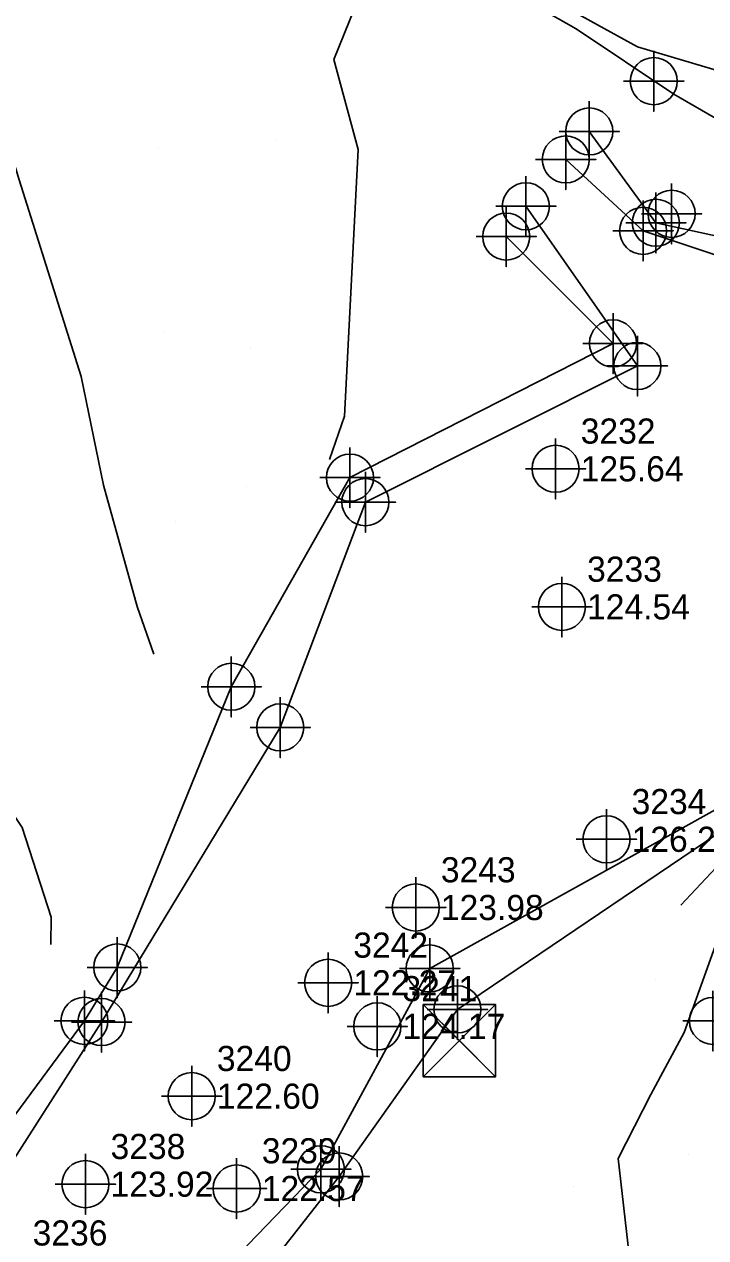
# Model space of a CAD drawing. Extents: x 2312183 to 2312663, y 819676 to 820746.
# Drawn here: x 2312397.7 to 2312465.5, y 820065.9 to 820186.5 of the extents above; entities that cross this region are included whole.
import ezdxf

# ---------------------------------------------------------------- set-up
doc = ezdxf.new("R2010")
doc.units = 0
for name, color, linetype in [('CTL Bench Mark CELL', 7, 'Continuous'), ('Exist DTM Breakline', 7, 'Continuous'), ('Exist DTM Breakline Cogo Point CELL', 7, 'Continuous'), ('Exist DTM Regular Point CELL', 7, 'Continuous'), ('Exist DTM Regular Point Underwater CELL', 7, 'Continuous'), ('Exist DTM Regular Point Underwater Cogo Elevation', 7, 'Continuous'), ('Exist DTM Regular Point Underwater Cogo Number', 7, 'Continuous'), ('Exist Hydro Stream or Body of Water', 7, 'Continuous'), ('Exist Hydro Stream or Body of Water Cogo Point CELL', 7, 'Continuous'), ('PH Exist DTM Breakline', 7, 'Continuous'), ('PH Exist DTM Point', 7, 'Continuous')]:
    doc.layers.add(name, color=color, linetype=linetype)

msp = doc.modelspace()

# ---------------------------------------------------------------- linework, layer by layer
at = {"layer": 'CTL Bench Mark CELL'}
msp.add_line((2312441.01, 820085.5), (2312441.01, 820085.5), dxfattribs=at)
msp.add_lwpolyline([(2312437.41, 820089.08), (2312444.6, 820089.08), (2312444.6, 820081.9), (2312437.41, 820081.9)], close=True, dxfattribs=at)
for points in [[(2312444.6, 820089.08), (2312437.41, 820081.9), (2312441.01, 820085.49), (2312444.6, 820081.9), (2312437.41, 820089.08)], [(2312441.01, 820085.49), (2312444.6, 820089.08), (2312437.41, 820089.08), (2312441.01, 820085.49)], [(2312441.01, 820085.49), (2312437.41, 820081.9), (2312444.6, 820081.9), (2312441.01, 820085.49)]]:
    msp.add_lwpolyline(points, dxfattribs=at)
at = {"layer": 'Exist DTM Breakline'}
for points in [[(2312453.92, 820175.89), (2312460.54, 820166.81), (2312494.29, 820159.45), (2312521.51, 820151.72), (2312518.42, 820162.59), (2312517.14, 820177.02)], [(2312445.66, 820165.44), (2312456.28, 820154.82), (2312430.12, 820141.47), (2312418.32, 820120.68), (2312406.98, 820092.77), (2312403.71, 820087.46)], [(2312398.6, 820034.89), (2312415.76, 820055.03), (2312429.05, 820071.99), (2312440.81, 820088.6), (2312469.05, 820107.68)], [(2312403.71, 820087.46), (2312374.49, 820047.93)]]:
    msp.add_lwpolyline(points, dxfattribs=at)
at = {"layer": 'Exist DTM Breakline Cogo Point CELL'}
for points in [[(2312453.92, 820178.89), (2312453.92, 820172.89), (2312453.92, 820175.89), (2312456.92, 820175.89), (2312450.92, 820175.89)], [(2312460.54, 820169.81), (2312460.54, 820163.81), (2312460.54, 820166.81), (2312463.54, 820166.81), (2312457.54, 820166.81)], [(2312445.66, 820168.44), (2312445.66, 820162.44), (2312445.66, 820165.44), (2312448.66, 820165.44), (2312442.66, 820165.44)], [(2312456.28, 820157.82), (2312456.28, 820151.82), (2312456.28, 820154.82), (2312459.28, 820154.82), (2312453.28, 820154.82)], [(2312430.12, 820144.47), (2312430.12, 820138.47), (2312430.12, 820141.47), (2312433.12, 820141.47), (2312427.12, 820141.47)], [(2312418.32, 820123.68), (2312418.32, 820117.68), (2312418.32, 820120.68), (2312421.32, 820120.68), (2312415.32, 820120.68)], [(2312406.98, 820095.77), (2312406.98, 820089.77), (2312406.98, 820092.77), (2312409.98, 820092.77), (2312403.98, 820092.77)], [(2312440.81, 820091.6), (2312440.81, 820085.6), (2312440.81, 820088.6), (2312443.81, 820088.6), (2312437.81, 820088.6)], [(2312403.71, 820090.46), (2312403.71, 820084.46), (2312403.71, 820087.46), (2312406.71, 820087.46), (2312400.71, 820087.46)], [(2312429.05, 820074.99), (2312429.05, 820068.99), (2312429.05, 820071.99), (2312432.05, 820071.99), (2312426.05, 820071.99)]]:
    msp.add_lwpolyline(points, dxfattribs=at)
for centre in [(2312453.92, 820175.89), (2312460.54, 820166.81), (2312445.66, 820165.44), (2312456.28, 820154.82), (2312430.12, 820141.47), (2312418.32, 820120.68), (2312406.98, 820092.77), (2312440.81, 820088.6), (2312403.71, 820087.46), (2312429.05, 820071.99)]:
    msp.add_circle(centre, 2.34, dxfattribs=at)
at = {"layer": 'Exist DTM Regular Point CELL'}
for points in [[(2312460.33, 820183.89), (2312460.33, 820177.89), (2312460.33, 820180.89), (2312463.33, 820180.89), (2312457.33, 820180.89)], [(2312462.11, 820170.7), (2312462.11, 820164.7), (2312462.11, 820167.7), (2312465.11, 820167.7), (2312459.11, 820167.7)], [(2312466.22, 820090.45), (2312466.22, 820084.45), (2312466.22, 820087.45), (2312469.22, 820087.45), (2312463.22, 820087.45)]]:
    msp.add_lwpolyline(points, dxfattribs=at)
for centre in [(2312460.33, 820180.89), (2312462.11, 820167.7), (2312466.22, 820087.45)]:
    msp.add_circle(centre, 2.34, dxfattribs=at)
at = {"layer": 'Exist DTM Regular Point Underwater CELL'}
for points in [[(2312450.57, 820145.35), (2312450.57, 820139.35), (2312450.57, 820142.35), (2312453.57, 820142.35), (2312447.57, 820142.35)], [(2312451.2, 820131.62), (2312451.2, 820125.62), (2312451.2, 820128.62), (2312454.2, 820128.62), (2312448.2, 820128.62)], [(2312455.63, 820108.51), (2312455.63, 820102.51), (2312455.63, 820105.51), (2312458.63, 820105.51), (2312452.63, 820105.51)], [(2312436.66, 820101.73), (2312436.66, 820095.73), (2312436.66, 820098.73), (2312439.66, 820098.73), (2312433.66, 820098.73)], [(2312427.95, 820094.24), (2312427.95, 820088.24), (2312427.95, 820091.24), (2312430.95, 820091.24), (2312424.95, 820091.24)], [(2312432.84, 820089.91), (2312432.84, 820083.91), (2312432.84, 820086.91), (2312435.84, 820086.91), (2312429.84, 820086.91)], [(2312414.38, 820082.97), (2312414.38, 820076.97), (2312414.38, 820079.97), (2312417.38, 820079.97), (2312411.38, 820079.97)], [(2312403.81, 820074.22), (2312403.81, 820068.22), (2312403.81, 820071.22), (2312406.81, 820071.22), (2312400.81, 820071.22)], [(2312418.85, 820073.79), (2312418.85, 820067.79), (2312418.85, 820070.79), (2312421.85, 820070.79), (2312415.85, 820070.79)]]:
    msp.add_lwpolyline(points, dxfattribs=at)
for centre in [(2312450.57, 820142.35), (2312451.2, 820128.62), (2312455.63, 820105.51), (2312436.66, 820098.73), (2312427.95, 820091.24), (2312432.84, 820086.91), (2312414.38, 820079.97), (2312403.81, 820071.22), (2312418.85, 820070.79)]:
    msp.add_circle(centre, 2.34, dxfattribs=at)
at = {"layer": 'Exist Hydro Stream or Body of Water'}
for points in [[(2312451.58, 820173.11), (2312459.27, 820166.01), (2312491.52, 820155.27), (2312524.63, 820151.17), (2312520.55, 820163.08), (2312522.64, 820179.93)], [(2312447.61, 820168.45), (2312458.7, 820152.57), (2312431.65, 820139.03), (2312423.18, 820116.64), (2312405.41, 820087.34)], [(2312393.18, 820036.93), (2312414.57, 820059.59), (2312427.23, 820072.7), (2312438.05, 820092.67), (2312468.54, 820109.59), (2312503.07, 820119.67), (2312550.88, 820117.01)], [(2312405.41, 820087.34), (2312377.81, 820044.19)]]:
    msp.add_lwpolyline(points, dxfattribs=at)
at = {"layer": 'Exist Hydro Stream or Body of Water Cogo Point CELL'}
for points in [[(2312448.58, 820173.11), (2312454.58, 820173.11), (2312451.58, 820173.11), (2312451.58, 820170.11), (2312451.58, 820176.11)], [(2312444.61, 820168.45), (2312450.61, 820168.45), (2312447.61, 820168.45), (2312447.61, 820165.45), (2312447.61, 820171.45)], [(2312456.27, 820166.01), (2312462.27, 820166.01), (2312459.27, 820166.01), (2312459.27, 820163.01), (2312459.27, 820169.01)], [(2312455.7, 820152.57), (2312461.7, 820152.57), (2312458.7, 820152.57), (2312458.7, 820149.57), (2312458.7, 820155.57)], [(2312428.65, 820139.03), (2312434.65, 820139.03), (2312431.65, 820139.03), (2312431.65, 820136.03), (2312431.65, 820142.03)], [(2312420.18, 820116.64), (2312426.18, 820116.64), (2312423.18, 820116.64), (2312423.18, 820113.64), (2312423.18, 820119.64)], [(2312435.05, 820092.67), (2312441.05, 820092.67), (2312438.05, 820092.67), (2312438.05, 820089.67), (2312438.05, 820095.67)], [(2312402.41, 820087.34), (2312408.41, 820087.34), (2312405.41, 820087.34), (2312405.41, 820084.34), (2312405.41, 820090.34)], [(2312424.23, 820072.7), (2312430.23, 820072.7), (2312427.23, 820072.7), (2312427.23, 820069.7), (2312427.23, 820075.7)]]:
    msp.add_lwpolyline(points, dxfattribs=at)
for centre in [(2312451.58, 820173.11), (2312447.61, 820168.45), (2312459.27, 820166.01), (2312458.7, 820152.57), (2312431.65, 820139.03), (2312423.18, 820116.64), (2312438.05, 820092.67), (2312405.41, 820087.34), (2312427.23, 820072.7)]:
    msp.add_circle(centre, 2.34, dxfattribs=at)
at = {"layer": 'PH Exist DTM Breakline'}
for points in [[(2312428.09, 820143.26), (2312429.58, 820147.58), (2312430.95, 820174.1), (2312428.5, 820183.06), (2312431.62, 820190.77), (2312435.54, 820194.22), (2312439.28, 820195.43), (2312442.83, 820191.67), (2312452.63, 820186.08), (2312462.34, 820179.59)], [(2312443.92, 820193.42), (2312449.14, 820189.59), (2312458.71, 820184.29), (2312471.76, 820180.42), (2312480.71, 820178.26), (2312488.13, 820176.64), (2312494.81, 820169.91), (2312498.34, 820165.17)], [(2312393.11, 820184.52), (2312397.23, 820171.07), (2312403.37, 820151.51), (2312405.61, 820140.72), (2312408.94, 820128.67), (2312410.62, 820123.93)], [(2312462.34, 820179.59), (2312482.6, 820167.87)], [(2312400.38, 820095.04), (2312400.39, 820097.78), (2312397.53, 820106.67), (2312390.94, 820116.39), (2312374.44, 820130.67), (2312365.88, 820132.63), (2312345.69, 820141.73)], [(2312500.08, 820108.06), (2312496.36, 820108.67), (2312492.14, 820109.57), (2312471.51, 820107.11), (2312470.52, 820106.81), (2312467.01, 820103.19), (2312463.02, 820098.96)], [(2312468.58, 820100.89), (2312463.34, 820086.29), (2312460.04, 820080.12), (2312456.79, 820073.77), (2312457.87, 820064.19), (2312460.28, 820052.1), (2312461.5, 820043.97), (2312462.94, 820036.24), (2312464.44, 820024.72), (2312467.71, 820007.01), (2312471.31, 819991.07), (2312472.67, 819975.28), (2312474.3, 819960.8), (2312475.94, 819945.72), (2312478.04, 819932.21)]]:
    msp.add_lwpolyline(points, dxfattribs=at)
at = {"layer": 'PH Exist DTM Point'}
for p, q in [((2312422.8, 820175.08), (2312422.8, 820175.08)), ((2312411.03, 820174.29), (2312411.03, 820174.29)), ((2312411.59, 820155.88), (2312411.59, 820155.88)), ((2312420.27, 820154.29), (2312420.27, 820154.29)), ((2312419.86, 820140.54), (2312419.86, 820140.54)), ((2312412.77, 820137.08), (2312412.77, 820137.08)), ((2312460.53, 820091.58), (2312460.53, 820091.58)), ((2312463.8, 820074.21), (2312463.8, 820074.21)), ((2312452.37, 820071.03), (2312452.37, 820071.03))]:
    msp.add_line(p, q, dxfattribs=at)

# ---------------------------------------------------------------- texts
at = {"layer": 'Exist DTM Regular Point Underwater Cogo Elevation'}
for s, p in [('125.64', (2312453.07, 820141.1)), ('124.54', (2312453.7, 820127.37)), ('126.23', (2312458.13, 820104.26)), ('123.98', (2312439.16, 820097.48)), ('122.27', (2312430.45, 820089.99)), ('124.17', (2312435.34, 820085.66)), ('122.60', (2312416.88, 820078.72)), ('123.92', (2312406.31, 820069.97)), ('122.57', (2312421.35, 820069.54))]:
    msp.add_text(s, height=2.5, dxfattribs=at).set_placement(p)
at = {"layer": 'Exist DTM Regular Point Underwater Cogo Number'}
for s, p in [('3232', (2312453.07, 820144.85)), ('3233', (2312453.7, 820131.12)), ('3234', (2312458.13, 820108.01)), ('3243', (2312439.16, 820101.23)), ('3242', (2312430.45, 820093.74)), ('3241', (2312435.34, 820089.41)), ('3240', (2312416.88, 820082.47)), ('3238', (2312406.31, 820073.72)), ('3239', (2312421.35, 820073.29)), ('3236', (2312398.56, 820065.12))]:
    msp.add_text(s, height=2.5, dxfattribs=at).set_placement(p)

doc.saveas('drawing.dxf')
